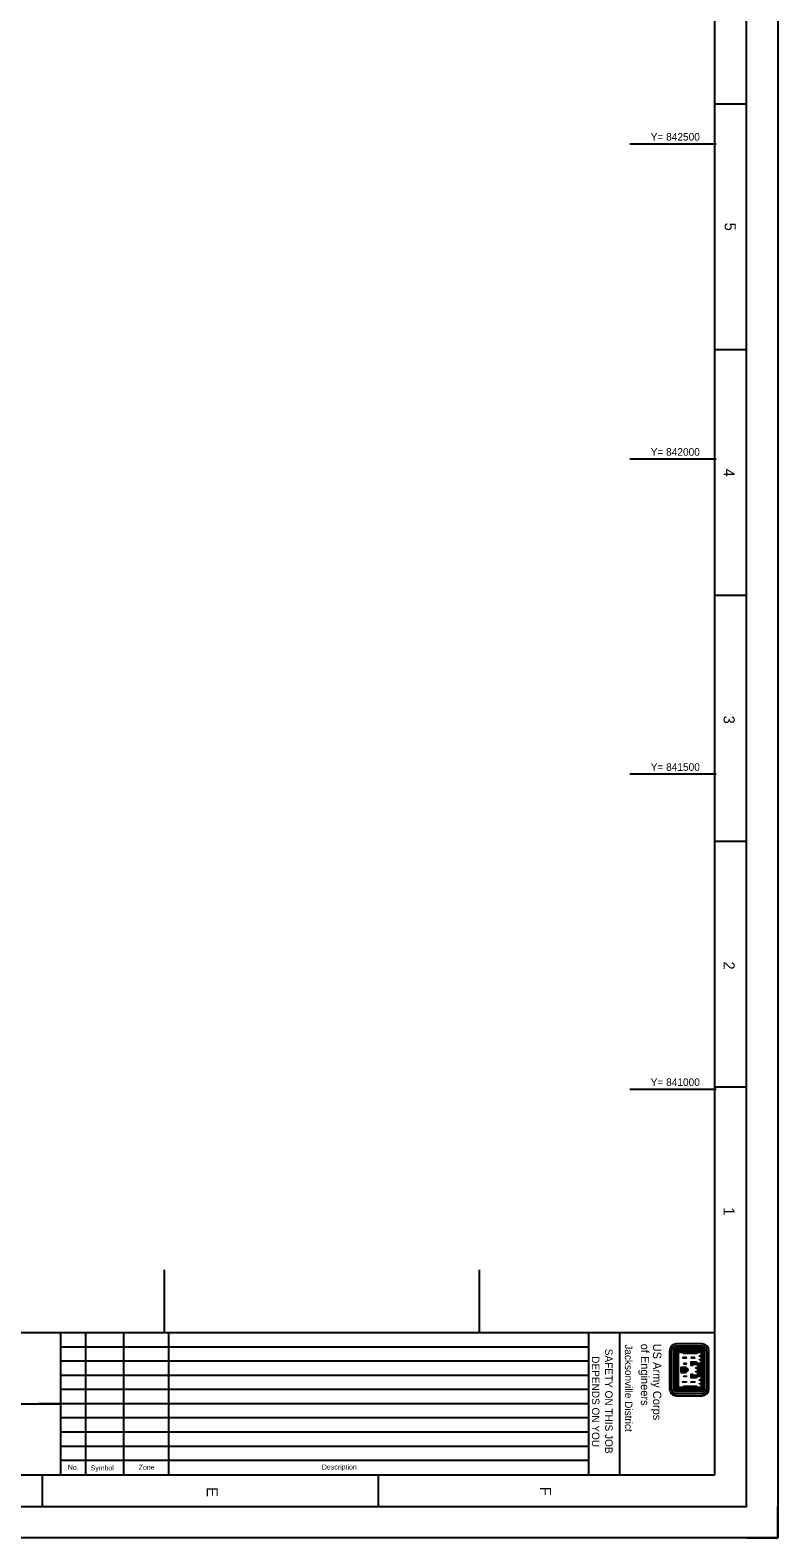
# Model space of a CAD drawing. Extents: x 583073 to 586473, y 840288 to 844688.
# Drawn here: x 585287 to 586473, y 840288 to 842680 of the extents above; entities that cross this region are included whole.
import ezdxf

# ---------------------------------------------------------------- set-up
doc = ezdxf.new("R2010")
doc.units = 0
for name, color, linetype in [('G-ANNO-NPLT', 7, 'Continuous'), ('G-ANNO-TEXT-LOGO', 7, 'Continuous'), ('G-ANNO-TEXT-TTLB', 7, 'Continuous'), ('G-ANNO-TTLB', 7, 'Continuous'), ('V-TOPO-COOR-STAT', 7, 'Continuous')]:
    doc.layers.add(name, color=color, linetype=linetype)

msp = doc.modelspace()

# ---------------------------------------------------------------- linework, layer by layer
at = {"layer": 'G-ANNO-NPLT'}
msp.add_lwpolyline([(586473.2, 844688), (586473.2, 840288), (583073.2, 840288), (583073.2, 844688)], close=True, dxfattribs=at)
msp.add_lwpolyline([(586423.2, 840288), (586473.2, 840288), (586473.2, 840338)], dxfattribs=at)
at = {"layer": 'G-ANNO-TEXT-LOGO'}
for p, q in [((586301.3, 840585), (586301.3, 840524.2)), ((586304.6, 840524.2), (586304.6, 840585)), ((586308.1, 840524.2), (586308.1, 840585)), ((586308.9, 840524.2), (586308.9, 840585)), ((586309.8, 840524.2), (586309.8, 840585)), ((586310.7, 840524.2), (586310.7, 840585)), ((586311.5, 840524.2), (586311.5, 840585)), ((586353.1, 840595.7), (586312.1, 840595.7)), ((586312.1, 840592.5), (586353.1, 840592.5)), ((586353.1, 840589), (586312.1, 840589)), ((586353.1, 840588.1), (586312.1, 840588.1)), ((586353.1, 840587.3), (586312.1, 840587.3)), ((586353.1, 840586.4), (586312.1, 840586.4)), ((586353.1, 840585.5), (586312.1, 840585.5)), ((586312.4, 840524.6), (586312.4, 840584.6)), ((586353.1, 840584.6), (586312.4, 840584.6)), ((586313.3, 840525.4), (586313.3, 840583.8)), ((586353.1, 840583.8), (586313.3, 840583.8)), ((586344.4, 840583.1), (586323.4, 840583.1)), ((586353.7, 840524.2), (586353.7, 840585)), ((586354.6, 840524.2), (586354.6, 840585)), ((586355.4, 840524.2), (586355.4, 840585)), ((586356.3, 840524.2), (586356.3, 840585)), ((586357.2, 840524.2), (586357.2, 840585)), ((586360.6, 840585), (586360.6, 840524.2)), ((586363.8, 840524.2), (586363.8, 840585)), ((586343.5, 840582.2), (586324.4, 840582.2)), ((586347.7, 840563.9), (586347.7, 840545.3)), ((586348.6, 840563.9), (586348.6, 840545.3)), ((586349.4, 840563.9), (586349.4, 840545.3)), ((586350.3, 840563.9), (586350.3, 840545.3)), ((586351.2, 840563.9), (586351.2, 840545.3)), ((586352, 840563.9), (586352, 840545.3)), ((586352.9, 840563.9), (586352.9, 840545.3)), ((586319.2, 840558.6), (586325.9, 840558.6)), ((586319.2, 840558.6), (586319.2, 840550.6)), ((586319.2, 840557.8), (586325.9, 840557.8)), ((586319.2, 840556.9), (586325.9, 840556.9)), ((586319.2, 840556), (586325.9, 840556)), ((586319.2, 840555.2), (586325.9, 840555.2)), ((586319.2, 840554), (586325.9, 840554)), ((586319.2, 840553.2), (586325.9, 840553.2)), ((586319.2, 840552.3), (586325.9, 840552.3)), ((586319.2, 840551.4), (586325.9, 840551.4)), ((586319.2, 840550.6), (586325.9, 840550.6)), ((586353.1, 840523.7), (586312.1, 840523.7)), ((586353.1, 840522.8), (586312.1, 840522.8)), ((586353.1, 840522), (586312.1, 840522)), ((586353.1, 840521.1), (586312.1, 840521.1)), ((586353.1, 840520.2), (586312.1, 840520.2)), ((586353.1, 840516.8), (586312.1, 840516.8)), ((586312.1, 840513.5), (586353.1, 840513.5)), ((586353.1, 840524.6), (586312.4, 840524.6)), ((586353.1, 840525.4), (586313.3, 840525.4)), ((586344.3, 840526.1), (586323.5, 840526.1)), ((586343.5, 840527), (586324.4, 840527))]:
    msp.add_line(p, q, dxfattribs=at)
for points in [[(586353.1, 840583.1), (586345.2, 840583.1), (586343.5, 840581.4), (586324.4, 840581.4), (586322.6, 840583.1), (586313.9, 840583.1), (586313.9, 840526.1), (586322.6, 840526.1), (586324.4, 840527.9), (586343.5, 840527.9), (586345.2, 840526.1), (586353.1, 840526.1), (586353.1, 840533.6), (586353.1, 840539.4), (586353.1, 840544.8), (586345.2, 840544.8), (586343.5, 840542.9), (586336.5, 840542.9), (586336.5, 840547.1), (586337.2, 840547.1), (586339, 840545.3), (586346.8, 840545.3), (586346.8, 840552.8), (586346.8, 840558.6), (586346.8, 840563.9), (586339, 840563.9), (586337.2, 840562.1), (586336.5, 840562.1), (586336.5, 840566.3), (586343.5, 840566.3), (586345.2, 840564.5), (586353.1, 840564.5), (586353.1, 840572), (586353.1, 840577.8), (586353.1, 840583.1)], [(586352.2, 840582.3), (586345.6, 840582.3), (586343.8, 840580.5), (586324, 840580.5), (586322.2, 840582.3), (586314.8, 840582.3), (586314.8, 840526.9), (586322.2, 840526.9), (586324, 840528.8), (586343.8, 840528.8), (586345.6, 840526.9), (586352.2, 840526.9), (586352.2, 840532.3), (586349.1, 840532.3), (586349.1, 840532.8), (586352.2, 840532.8), (586352.2, 840538.1), (586349.1, 840538.1), (586349.1, 840538.5), (586352.2, 840538.5), (586352.2, 840543.9), (586345.6, 840543.9), (586343.8, 840542.1), (586335.7, 840542.1), (586335.7, 840547.9), (586337.6, 840547.9), (586339.4, 840546.1), (586346, 840546.1), (586346, 840551.5), (586342.9, 840551.5), (586342.9, 840551.9), (586346, 840551.9), (586346, 840557.3), (586342.9, 840557.3), (586342.9, 840557.8), (586346, 840557.8), (586346, 840563.1), (586339.4, 840563.1), (586337.6, 840561.3), (586335.7, 840561.3), (586335.7, 840567.1), (586343.8, 840567.1), (586345.6, 840565.3), (586352.2, 840565.3), (586352.2, 840570.6), (586349.1, 840570.6), (586349.1, 840571.1), (586352.2, 840571.1), (586352.2, 840576.5), (586349.1, 840576.5), (586349.1, 840576.9), (586352.2, 840576.9), (586352.2, 840582.3)], [(586328.2, 840574.1), (586322.3, 840574.1), (586322.3, 840573.5), (586328.2, 840573.5), (586328.2, 840574.1)], [(586328.2, 840564.9), (586324.1, 840564.9), (586324.1, 840564.4), (586328.2, 840564.4), (586328.2, 840564.9)], [(586341.5, 840574.1), (586335.7, 840574.1), (586335.7, 840573.5), (586341.5, 840573.5), (586341.5, 840574.1)], [(586343.6, 840564.9), (586343.1, 840565.4), (586337.4, 840565.4), (586337.4, 840563.5), (586338.7, 840564.8), (586343.7, 840564.8)], [(586328.2, 840535.2), (586322.3, 840535.2), (586322.3, 840535.7), (586328.2, 840535.7), (586328.2, 840535.2)], [(586328.2, 840544.3), (586324.1, 840544.3), (586324.1, 840544.8), (586328.2, 840544.8), (586328.2, 840544.3)], [(586341.5, 840535.2), (586335.7, 840535.2), (586335.7, 840535.7), (586341.5, 840535.7), (586341.5, 840535.2)], [(586343.6, 840544.3), (586343.1, 840543.8), (586337.4, 840543.8), (586337.4, 840545.6), (586338.7, 840544.4), (586343.7, 840544.4)]]:
    msp.add_lwpolyline(points, dxfattribs=at)
for centre, major_axis, start_param, end_param in [((586312.1, 840585), (0, 10.7), 6.28317, 7.853966), ((586312.1, 840585), (0, 7.49), 6.28317, 7.853966), ((586312.1, 840585), (0, 4.02), 6.28317, 7.853966), ((586312.1, 840585), (0, 3.15), 6.28317, 7.853966), ((586312.1, 840585), (0, 2.28), 6.28317, 7.853966), ((586312.1, 840585), (0, 1.41), 6.28317, 7.853966), ((586312.1, 840585), (0, 0.546), 6.28317, 7.853966), ((586353.1, 840585), (0, -10.7), 1.57078, 3.141576), ((586353.1, 840585), (0, -7.49), 1.57078, 3.141576), ((586353.1, 840585), (0, -4.02), 1.57078, 3.141576), ((586353.1, 840585), (0, -3.15), 1.57078, 3.141576), ((586353.1, 840585), (0, -2.28), 1.57078, 3.141576), ((586353.1, 840585), (0, -1.41), 1.57078, 3.141576), ((586353.1, 840585), (0, -0.546), 1.57078, 3.141576), ((586325.5, 840556.1), (0, -2.08), 0.068794, 1.335689), ((586325.5, 840553.1), (0, 2.08), 4.947465, 6.214359), ((586325.5, 840553.1), (0, 3.82), 4.947465, 6.21436), ((586325.5, 840553.1), (0, 2.95), 4.947465, 6.21436), ((586325.5, 840556.1), (0, -2.95), 0.068794, 1.335689), ((586325.5, 840556.1), (0, -3.82), 0.068795, 1.335689), ((586325.5, 840553.1), (0, 4.69), 4.947465, 6.21436), ((586325.5, 840556.1), (0, -4.69), 0.068795, 1.335689), ((586325.5, 840553.1), (0, 5.55), 4.985832, 6.214359), ((586325.5, 840556.1), (0, -5.55), 0.068795, 1.29842), ((586312.1, 840524.2), (0, -10.7), 4.712373, 6.28317), ((586312.1, 840524.2), (0, 7.49), 1.570781, 3.141577), ((586312.1, 840524.2), (0, -4.02), 4.712373, 6.28317), ((586312.1, 840524.2), (0, -3.15), 4.712373, 6.28317), ((586312.1, 840524.2), (0, -2.28), 4.712373, 6.28317), ((586312.1, 840524.2), (0, -1.41), 4.712373, 6.28317), ((586312.1, 840524.2), (0, -0.546), 4.712373, 6.28317), ((586353.1, 840524.2), (0, -4.02), 6.283169, 7.853965), ((586353.1, 840524.2), (0, -3.15), 6.283169, 7.853965), ((586353.1, 840524.2), (0, -2.28), 6.283169, 7.853965), ((586353.1, 840524.2), (0, -1.41), 6.283169, 7.853965), ((586353.1, 840524.2), (0, -0.546), 6.283169, 7.853965), ((586353.1, 840524.2), (0, -10.7), 6.283169, 7.853965), ((586353.1, 840524.2), (0, -7.49), 6.28317, 7.853966)]:
    msp.add_ellipse(centre, major_axis=major_axis, ratio=0.99964, start_param=start_param, end_param=end_param, dxfattribs=at)
at = {"layer": 'G-ANNO-TTLB'}
for p, q in [((586423.2, 842563), (586373.2, 842563)), ((586423.2, 842173), (586373.2, 842173)), ((586423.2, 841783), (586373.2, 841783)), ((586423.2, 841393), (586373.2, 841393)), ((586423.2, 841003), (586373.2, 841003)), ((586373.2, 840613.1), (583173.2, 840613.1)), ((585334.9, 840613), (585334.9, 840388)), ((585374.8, 840613), (585374.8, 840388)), ((585434.8, 840613), (585434.8, 840388)), ((585506, 840613), (585506, 840388)), ((586172.9, 840613.7), (586172.9, 840388.7)), ((586222, 840613), (586222, 840388)), ((586172.9, 840590.7), (585334.9, 840590.7)), ((586172.9, 840568.2), (585334.9, 840568.2)), ((586172.9, 840545.7), (585334.9, 840545.7)), ((586172.9, 840523.2), (585334.9, 840523.2)), ((584475.4, 840501.2), (585334.9, 840500.5)), ((585334.9, 840500.5), (585299.5, 840500.6)), ((586172.9, 840500.7), (585334.9, 840500.7)), ((586172.9, 840478.2), (585334.9, 840478.2)), ((586172.9, 840455.7), (585334.9, 840455.7)), ((586172.9, 840433.2), (585334.9, 840433.2)), ((586172.9, 840410.7), (585334.9, 840410.7)), ((585306.4, 840338), (585306.4, 840388)), ((585839.7, 840338), (585839.7, 840388))]:
    msp.add_line(p, q, dxfattribs=at)
for points in [[(583123.2, 844638), (583123.2, 840338), (586423.2, 840338), (586423.2, 844638)], [(586373.2, 840388), (586373.2, 844513), (583173.2, 844513), (583173.2, 840388)]]:
    msp.add_lwpolyline(points, close=True, dxfattribs=at)
at = {"layer": 'V-TOPO-COOR-STAT'}
for p, q in [((586238.2, 842500), (586375.3, 842500)), ((586238.2, 842000), (586375.3, 842000)), ((586238.2, 841500), (586375.3, 841500)), ((586238.2, 841000), (586375.3, 841000)), ((585500, 840613.1), (585500, 840713.1)), ((586000, 840613.1), (586000, 840713.1))]:
    msp.add_line(p, q, dxfattribs=at)

# ---------------------------------------------------------------- texts
at = {"layer": 'G-ANNO-TEXT-TTLB'}
for s, height, rotation, p in [('SAFETY ON THIS JOB', 11.9, 270, (586199.1, 840588)), ('Jacksonville District', 11.9, 270, (586230.5, 840595.1)), ('of Engineers', 13.086, 270, (586255.8, 840596.1)), ('US Army Corps', 13.086, 270, (586275.2, 840596.1)), ('DEPENDS ON YOU', 11.9, 270, (586178.2, 840576.2)), ('No.', 8, 360, (585346.5, 840396)), ('Symbol', 8, 360, (585382.7, 840395)), ('Zone', 8, 360, (585459, 840396.1)), ('Description', 8, 360, (585749.7, 840396.4))]:
    msp.add_text(s, height=height, rotation=rotation, dxfattribs=at).set_placement(p)
at = {"layer": 'G-ANNO-TTLB'}
for s, p in [('5', (586388.9, 842374.8)), ('4', (586387.1, 841984.4)), ('3', (586387.1, 841592.6)), ('2', (586387.1, 841202.6)), ('1', (586387.1, 840812.6)), ('F', (586095.9, 840369.3)), ('E', (585567, 840368.5))]:
    msp.add_text(s, height=17.5, rotation=270, dxfattribs=at).set_placement(p)
at = {"layer": 'V-TOPO-COOR-STAT'}
for s, p in [('Y= 842500', (586271.4, 842505)), ('Y= 842000', (586271.4, 842005)), ('Y= 841500', (586271.4, 841505)), ('Y= 841000', (586271.4, 841005))]:
    msp.add_text(s, height=12, dxfattribs=at).set_placement(p)

doc.saveas('drawing.dxf')
